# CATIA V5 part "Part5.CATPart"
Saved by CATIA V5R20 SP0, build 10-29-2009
Part number: Part5
Bounding box of the stored display mesh (mm): x -5 to 5, y 21.212 to 35.357, z 48.284 to 78.284
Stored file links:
  C:\Documents and Settings\Media\Escritorio\GATO_ALAMBRICO\Part5.CATPart
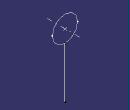
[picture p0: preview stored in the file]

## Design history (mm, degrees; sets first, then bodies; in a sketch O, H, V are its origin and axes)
Set1
  Line1: type Normal, RefPoint DatumPoint1, RefSkin xy-plane, Start 0, End 20
  DatumPoint1
  Point1: type OnCurve, Support Line1, Length 5, RefPoint vertex of Line1
  Circle1: type CtrRad, Start 0, End 180, Radius 5, Center Point1, Support zx-plane, FirstDirection (-1, 0, 0)
  AxisLine1: Element Circle1
Body1 (main body)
